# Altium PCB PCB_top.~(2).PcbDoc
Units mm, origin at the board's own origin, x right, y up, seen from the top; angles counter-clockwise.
Board outline 61.6 x 61.6 mm, 4 copper layers (TOP, 2, 3, BOTTOM), stack 1.719 mm thick; 9 components, 48 nets, 62 pads, 0 vias.
Unrouted connection lines stored in the file: 38.
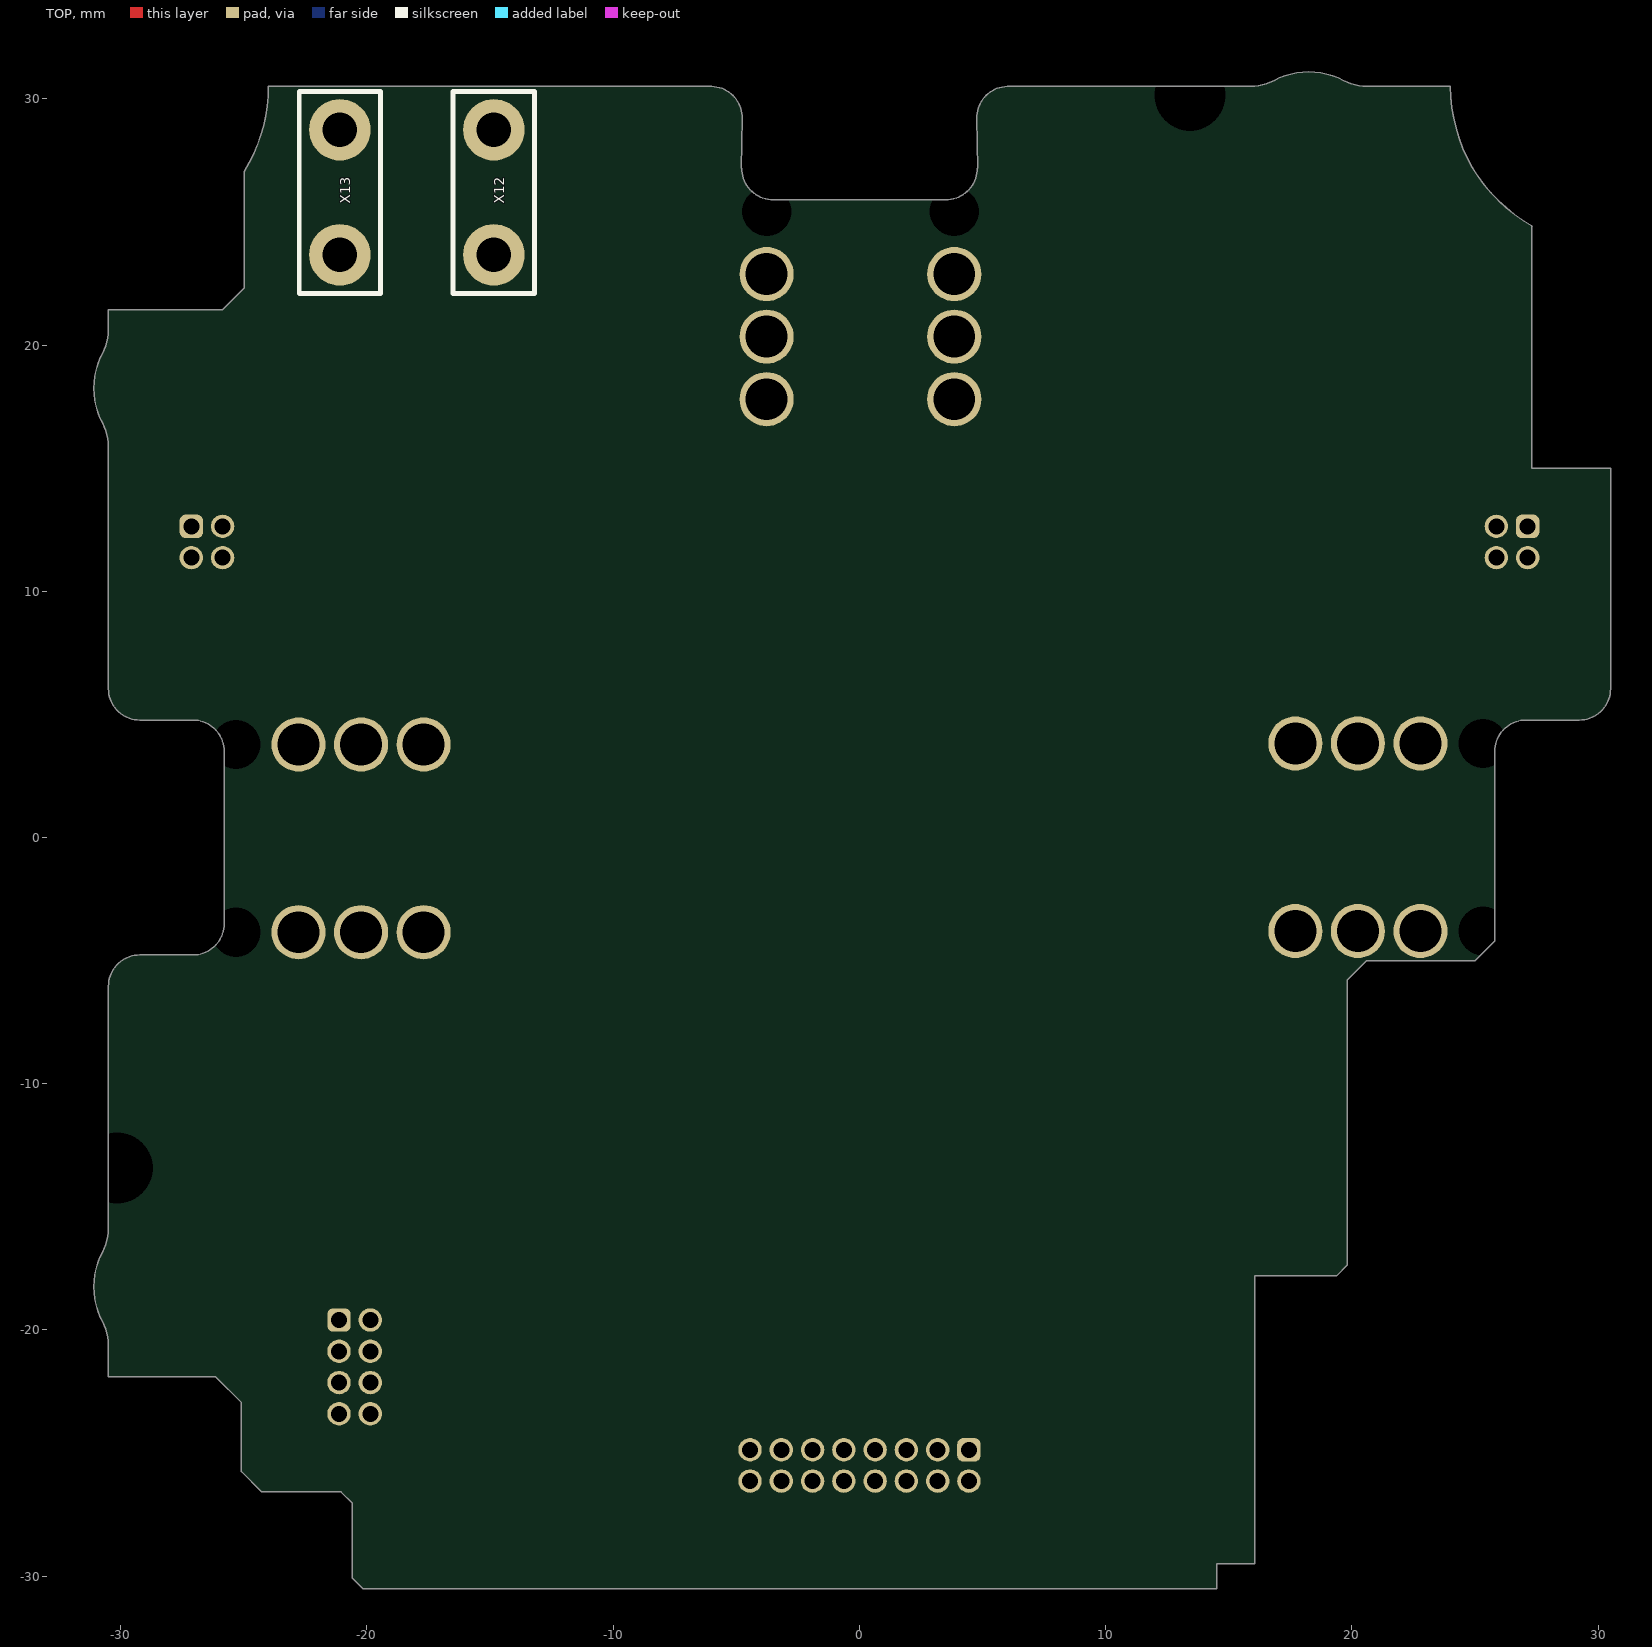
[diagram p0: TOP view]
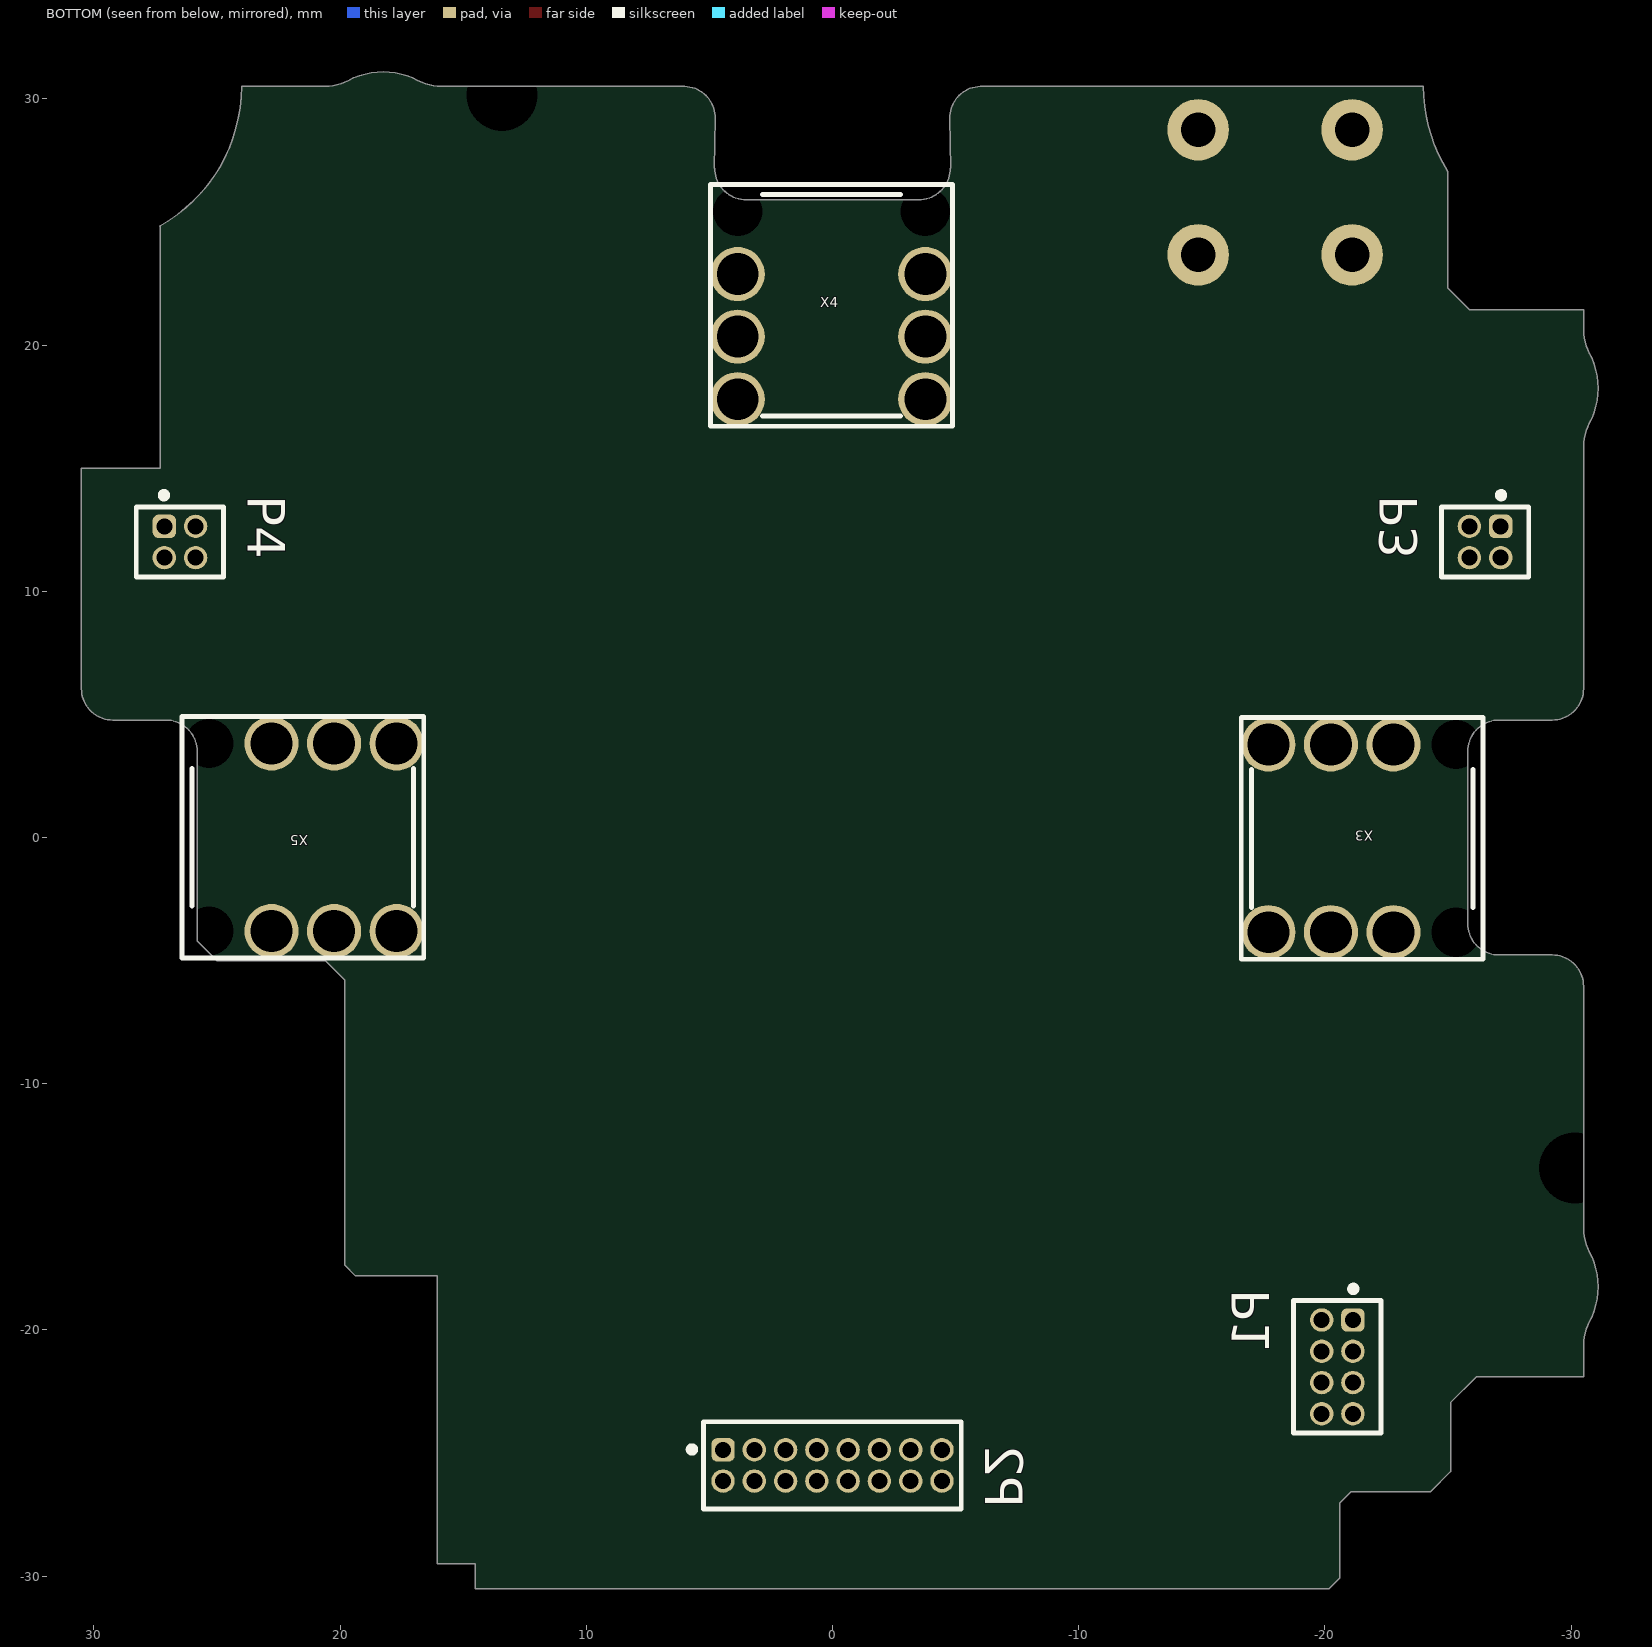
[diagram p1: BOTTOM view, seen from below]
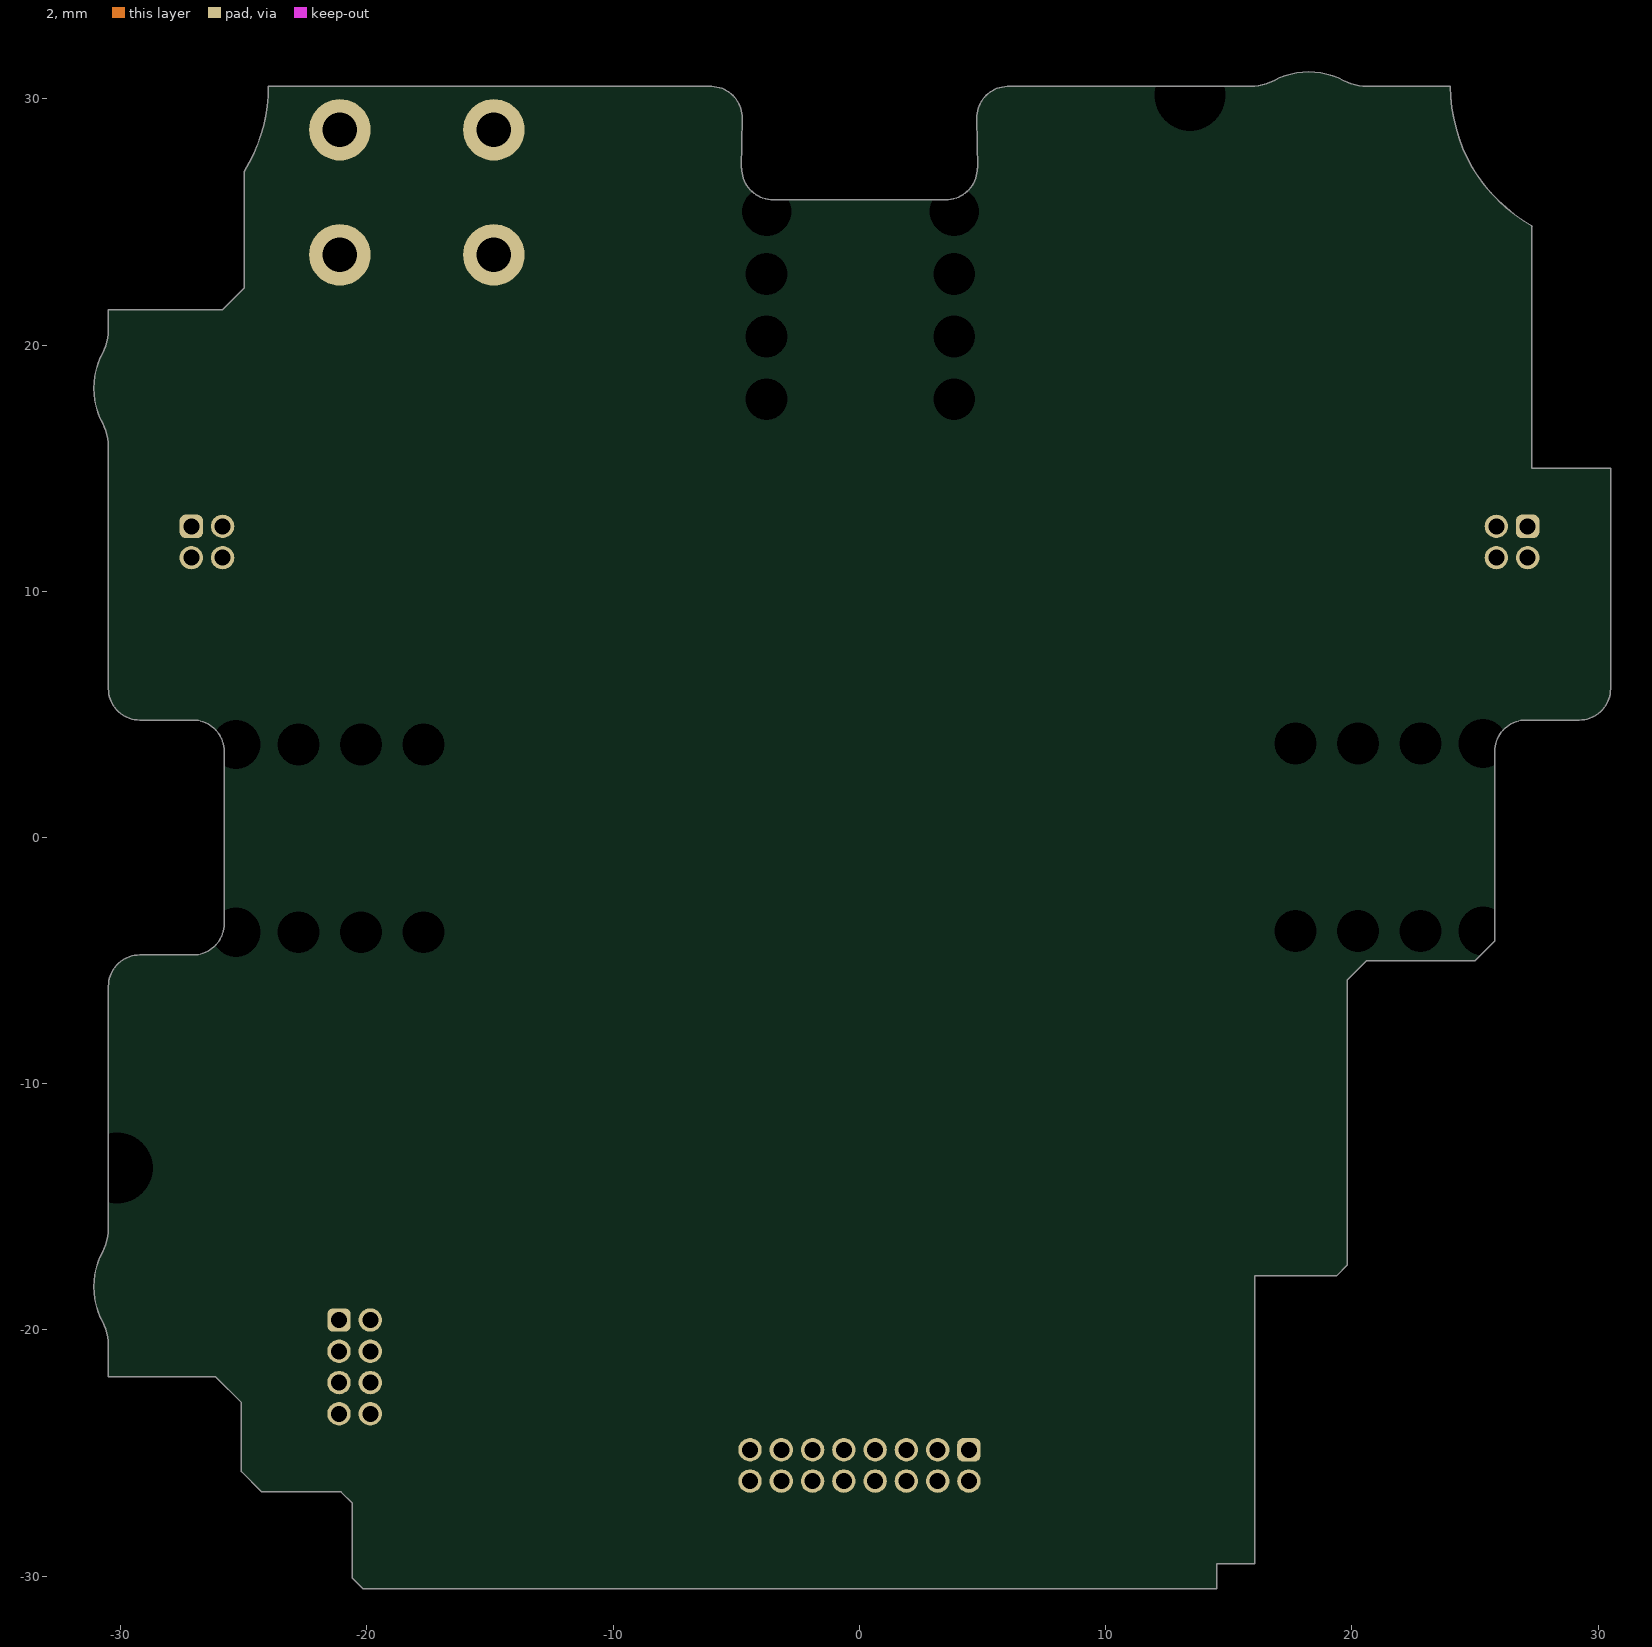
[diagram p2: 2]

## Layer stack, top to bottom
Top Solder: solder mask 0.01, Solder Resist, Dk 3.5
TOP: signal copper 0.07
Dielectric 1: prepreg 0.0711, PP-006, Dk 4.1
Dielectric 4: prepreg 0.2033, PP-006, Dk 4.1
2: signal copper 0.035
Dielectric 3: core 0.96, S1000-2, Dk 4.5
3: signal copper 0.035
Dielectric 2: prepreg 0.2033, PP-006, Dk 4.1
Dielectric 5: prepreg 0.0711, PP-006, Dk 4.1
BOTTOM: signal copper 0.07
Bottom Solder: solder mask 0.01, Solder Resist, Dk 3.5

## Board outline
-30.5,-20.612 ccw(c-32.5,-20.612) -30.738,-19.665 cw(c-28.095,-18.245) -30.738,-16.826 ccw(c-32.5,-15.879) -30.5,-15.879 -30.5,-6.04 cw(c-29.23,-6.04) -29.23,-4.77 -27.07,-4.77 ccw(c-27.07,-3.5) -25.8,-3.5 -25.8,3.5 ccw(c-27.07,3.5) -27.07,4.77 -29.23,4.77 cw(c-29.23,6.04) -30.5,6.04 -30.5,15.879 ccw(c-32.5,15.879) -30.738,16.826 cw(c-28.095,18.245) -30.738,19.665 ccw(c-32.5,20.612) -30.5,20.612 -30.5,21.442 -25.858,21.442 -24.988,22.312 -24.988,27.055 ccw(c-30.5,30.5) -24,30.5 -6,30.5 cw(c-6.034,29.233) -4.767,29.199 -4.799,27.185 -4.788,27.185 ccw(c-3.503,27.185) -3.503,25.9 3.503,25.9 ccw(c3.503,27.185) 4.788,27.185 4.799,27.185 4.767,29.199 cw(c6.034,29.233) 6,30.5 15.879,30.5 ccw(c15.879,32.5) 16.826,30.738 cw(c18.245,28.095) 19.665,30.738 ccw(c20.612,32.5) 20.612,30.5 24,30.5 ccw(c30.5,30.5) 27.318,24.832 27.3,24.842 27.3,15 30.5,15 30.5,6.04 cw(c29.23,6.04) 29.23,4.77 27.07,4.77 ccw(c27.07,3.5) 25.8,3.5 25.8,-4.205 25.005,-5 20.598,-5 19.8,-5.798 19.8,-17.373 19.368,-17.805 16.055,-17.805 16.055,-29.5 14.5,-29.5 14.5,-30.5 -20.175,-30.5 -20.6,-30.075 -20.6,-27.025 -21.05,-26.575 -24.275,-26.575 -25.1,-25.75 -25.1,-22.95 -26.15,-21.9 -30.5,-21.9

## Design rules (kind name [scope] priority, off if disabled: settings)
BoardOutlineClearance [All] p1: gap=0.5 ignorepadtopadclearanceinfootprint=FALSE
Clearance "Clearance TP Bottom" [InPadClass('Test pads') AND OnBottomLayer vs InPadClass('Test pads') AND OnBottomLayer] p1: gap=2.54 ignorepadtopadclearanceinfootprint=FALSE
Clearance "Clearance PE" [InNet('PE')] p2: gap=0.5 ignorepadtopadclearanceinfootprint=FALSE
Clearance "Clearance spacers" [InComponentClass('Spacer')] p3: gap=0.5 ignorepadtopadclearanceinfootprint=FALSE
Clearance "Clearance Polygon" [InPolygon vs InPolygon] p4: gap=0.5 ignorepadtopadclearanceinfootprint=FALSE
Clearance "Clearance All" [NOT InComponent('U1') AND NOT InPadClass('Exception pads')] p5: gap=0.2 ignorepadtopadclearanceinfootprint=FALSE
Clearance "Clearance Via" [IsVia vs IsPad And Not (InComponentClass('PowerComponents') Or InPadClass('Power pads'))] p6 off: gap=0.25 ignorepadtopadclearanceinfootprint=FALSE
ComponentClearance "ComponentClearance Wave Soldering" [InComponentClass('THT Components')] p1: gap=3 collisioncheckmode=3 verticalgap=2540 showdistances=TRUE
ComponentClearance "ComponentClearance Selective Soldering" [InComponentClass('Selective Soldering Component')] p2: gap=3 collisioncheckmode=3 verticalgap=2540 showdistances=TRUE
ComponentClearance [OnLayer('Top Layer') vs OnLayer('Top Layer')] p3: gap=0.203 collisioncheckmode=3 verticalgap=0.254 showdistances=FALSE
FabricationTestPointUsage TestPointUsage [InNetClass('All Nets')] p1 off: valid=0 allowmultiple=FALSE
FabricationTestpoint Testpoint [(InNetClass('All Nets')) And ((IsPad And (OnTopLayer Or OnBottomLayer)))] p1 off: side=2 testpointundercomponent=FALSE minsize=1 maxsize=2 preferedsize=1.2 minholesize=0 maxholesize=2 preferedholesize=1 testpointgrid=0.01 allowsidebottom=TRUE usegrid=TRUE gridtolerance=0
FanoutControl Fanout_BGA [IsBGA] p1: bgadir=Out bgaviamode=Centered fanoutstyle=Auto fanoutdirection=InThenOut viagrid=0.025 // Fanout_BGA (Default Rule)
FanoutControl Fanout_LCC [IsLCC] p2: bgadir=Out bgaviamode=Centered fanoutstyle=Auto fanoutdirection=InThenOut viagrid=0.025 // Fanout_LCC (Default Rule)
FanoutControl Fanout_SOIC [IsSOIC] p3: bgadir=Out bgaviamode=Centered fanoutstyle=Auto fanoutdirection=InThenOut viagrid=0.025 // Fanout_SOIC (Default Rule)
FanoutControl Fanout_Small [(CompPinCount < 5)] p4: bgadir=Out bgaviamode=Centered fanoutstyle=Auto fanoutdirection=InThenOut viagrid=0.025 // Fanout_Small (Default Rule)
FanoutControl Fanout_Default [All] p5: bgadir=Out bgaviamode=Centered fanoutstyle=Auto fanoutdirection=InThenOut viagrid=0.025 // Fanout_Default (Default Rule)
Height [All] p1: minheight=0 maxheight=40 prefheight=12.7
HoleSize [All] p1: absolutevalues=TRUE maxlimit=20 minlimit=0.15 maxpercent=80.000 minpercent=20.000
HoleToHoleClearance [All] p1: gap=0.15 allowstackedmicrovias=TRUE
MinimumAnnularRing [All] p1 off: minimumring=0.125
NetAntennae [All] p1 off: netantennaetolerance=0
PlaneClearance [All] p1: clearance=0.5
PlaneConnect [All] p1: planeconnectstyle=Direct reliefexpansion=0.508 reliefentries=4 reliefconductorwidth=0.254 reliefairgap=0.254
PolygonConnect "PolygonConnect Direct" [InPadClass('Direct pads')] p1: connectstyle=Direct reliefconductorwidth=0.254 reliefentries=4 polygonreliefangle="90 Angle" airgapwidth=0.254
PolygonConnect "PolygonConnect TestPads" [InPadClass('Test pads')] p2: connectstyle=Direct reliefconductorwidth=0.254 reliefentries=4 polygonreliefangle="90 Angle" airgapwidth=0.254
PolygonConnect PolygonConnect-PowerPads [InPadClass('Power pads')] p3: connectstyle=Relief reliefconductorwidth=1 reliefentries=4 polygonreliefangle="90 Angle" airgapwidth=0.2
PolygonConnect "PolygonConnect Via" [IsVia] p4: connectstyle=Direct reliefconductorwidth=0.254 reliefentries=4 polygonreliefangle="90 Angle" airgapwidth=0.254
PolygonConnect "PolygonConnect All" [All] p5: connectstyle=Relief reliefconductorwidth=0.3 reliefentries=4 polygonreliefangle="90 Angle" airgapwidth=0.25
RoutingCorners [All] p1: cornerstyle=45-Degree minsetback=2 maxsetback=2
RoutingVias [All] p1: holewidth=0.2 width=0.5 viastyle="Through Hole" minholewidth=0.2 minwidth=0.5 maxholewidth=1 maxwidth=2 useviatemplates=TRUE viatemplateguid#1={C91082AD-6814-4CF8-9952-BA175974D977} viatemplateguid#2={F9BC3B68-C7FA-485B-9147-DE2A793F0151} viatemplatename#1=v05h02 viatemplatename#2=v06h03
SilkToSolderMaskClearance SilkscreenOverComponentPads [IsPad] p1: minsilkscreentomaskgap=0.254 clearancetoexposedcopper=TRUE
SolderMaskExpansion [All] p1: expansion=0.1 istentingtop=FALSE
SupplyNets "Schematic Supply Nets" [InNet('24V/12V')] p1: voltage=0.000
SupplyNets "Schematic Supply Nets_2" [InNet('24V')] p2: voltage=0.000
SupplyNets "Schematic Supply Nets_3" [InNet('GND')] p3: voltage=0.000
SupplyNets "Schematic Supply Nets_1" [InNet('DC_LINK')] p4: voltage=0.000
SupplyNets "Schematic Supply Nets_9" [InNet('5V')] p5: voltage=0.000
Width [All] p1: maxlimit=10 minlimit=0.1 preferedwidth=0.25
14 further rules are at their usual default settings.

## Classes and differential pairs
pad class "Direct pads": X3-1 X4-1 X5-1
component class Power_Mosfet: X3 X4 X5
pad class "Power pads": X13-1
component class Main: P1 P2 P3 P4 X12 X13

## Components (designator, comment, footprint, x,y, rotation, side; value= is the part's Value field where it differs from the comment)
P1 "62200821121" 62200821121 -20.5,-21.5 r270 bottom locked
P2 "62201621121" 62201621121 0,-25.5 r180 bottom locked
P3 "62200421121" 62200421121#1 -26.5,12 r270 bottom
P4 "62200421121" 62200421121#2 26.5,12 r270 bottom locked
X3 "K_WURTH_7461063" FPR_K_1P_WURTH -21.51,-0.035 r270 bottom locked
X4 "K_WURTH_7461063" FPR_K_1P_WURTH 0.04,21.61 r180 bottom locked
X5 "K_WURTH_7461063" FPR_K_1P_WURTH 21.51,0.01 r90 bottom locked
X12 "C_TE_FASTON_6.3_P5.08" FPR_TAB_6.3_P5.08_Pokončni -14.85,26.2 r90 top locked
X13 "C_TE_FASTON_6.3_P5.08" FPR_TAB_6.3_P5.08_Pokončni -21.1,26.2 r90 top locked

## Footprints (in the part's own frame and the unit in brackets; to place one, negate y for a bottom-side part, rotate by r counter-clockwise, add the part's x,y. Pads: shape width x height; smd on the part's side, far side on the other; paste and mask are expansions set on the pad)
62200421121#1 [mm]
  rrect50% 0.95x0.95 hole 0.65: 1(-0.635,0.635)
  round 0.95 hole 0.65: 2(-0.635,-0.635) 3(0.635,0.635) 4(0.635,-0.635)
  silkscreen extent -2.02,-1.78 1.42,1.78, body extent -1.27,-1.7 1.27,1.7, height 5.33
62200421121#2 [mm]
  rrect50% 0.95x0.95 hole 0.65: 1(-0.635,-0.635)
  round 0.95 hole 0.65: 2(-0.635,0.635) 3(0.635,-0.635) 4(0.635,0.635)
  silkscreen extent -2.02,-1.78 1.42,1.78, body extent -1.27,-1.7 1.27,1.7, height 5.33
62200821121 [mm]
  rrect50% 0.95x0.95 hole 0.65: 1(-1.905,0.635)
  round 0.95 hole 0.65: 2(-1.905,-0.635) 3(-0.635,0.635) 4(-0.635,-0.635) 5(0.635,0.635) 6(0.635,-0.635) 7(1.905,0.635) 8(1.905,-0.635)
  silkscreen extent -3.29,-1.78 2.69,1.78, body extent -2.54,-1.7 2.54,1.7, height 5.33
62201621121 [mm]
  rrect50% 0.95x0.95 hole 0.65: 1(-4.445,0.635)
  round 0.95 hole 0.65: 2(-4.445,-0.635) 3(-3.175,0.635) 4(-3.175,-0.635) 5(-1.905,0.635) 6(-1.905,-0.635) 7(-0.635,0.635) 8(-0.635,-0.635) 9(0.635,0.635) 10(0.635,-0.635) 11(1.905,0.635) 12(1.905,-0.635) 13(3.175,0.635) 14(3.175,-0.635) 15(4.445,0.635) 16(4.445,-0.635)
  silkscreen extent -5.83,-1.78 5.23,1.78, body extent -5.08,-1.7 5.08,1.7, height 5.33
FPR_K_1P_WURTH [mm]
  round 2.2 / inner round 0 / far side round 2.2 hole 1.7: 1(-3.81,-1.27) 1(-3.81,-3.81) 1(-3.81,1.27) 1(3.81,-3.81) 1(3.81,-1.27) 1(3.81,1.27)
  round 0 hole 2 unplated: 1(-3.81,3.81) 1(3.81,3.81)
  silkscreen extent -4.91,-4.91 4.91,4.91, body extent -4.5,-4.5 4.5,4.5, height 14
FPR_TAB_6.3_P5.08_Pokončni [mm]
  round 2.5 hole 1.4: 1(-2.54,0) 1(2.54,0)
  silkscreen extent -4.1,-1.65 4.1,1.65, body extent -3.96,-1.54 3.96,1.54, height 10.21

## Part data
P1: library part CMP-1502-00947-4, "THT Vertical Pin Header WR-PHD, Pitch 1.27 mm, Dual Row, 8 pins", Color=Black, Contact Resistance=20mΩ, Current Rating=1A
P2: library part CMP-1502-00950-4, "THT Vertical Pin Header WR-PHD, Pitch 1.27 mm, Dual Row, 16 pins", Color=Black, Contact Resistance=20mΩ, Current Rating=1A
P3 P4: library part CMP-1502-00946-4, "THT Vertical Pin Header WR-PHD, Pitch 1.27 mm, Dual Row, 4 pins", Color=Black, Contact Resistance=20mΩ, Current Rating=1A
X3 X4 X5: library part K_WURTH_7461063-4, "Connector POWER Wurth 7461063", Current=160, Manufacturer="WURTH ELEKTRONIK", Manufacturer code=7461063, TemperatureGrade=-40...150, Voltage=300
X12 X13: library part C_TE_FASTON_6.3_P5.08-4, "FASTON 6.3 P5.08 Pokončni", Current=-, Manufacturer="TE CONNECTIVITY", Manufacturer code=1217136-1, TemperatureGrade="-30...110 °C", Voltage=/

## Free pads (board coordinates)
  round 0 hole 2.9 unplated paste-2539.97 mask+0.1: 107(-30.146,-13.422) 991(13.422,30.147)

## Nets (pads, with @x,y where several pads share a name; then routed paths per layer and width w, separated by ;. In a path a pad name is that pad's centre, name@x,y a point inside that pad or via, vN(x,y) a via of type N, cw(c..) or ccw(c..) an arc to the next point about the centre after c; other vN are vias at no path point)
5V: P1.7
24V/12V: P1.1 P1.2
DC_LINK: P3.2 P3.4 P4.2 P4.4
GATE_UH: 
GATE_UL: 
GATE_VH: 
GATE_VL: 
GATE_WH: 
GATE_WL: 
GND: P1.3 P1.5 P1.6 P2.3 P2.6 P2.10 P2.13 P2.14 P3.3 P4.1 P4.3 X13.1
I_D_SPI_MISO: P2.16
NetC7_1: 
NetC8_1: 
NetC9_1: 
NetC10_1: 
NetC10_2: 
NetC11_1: 
NetC11_2: 
NetC13_2: 
NetC14_1: 
NetC14_2: 
NetIC3_36: 
NetIC3_45: 
NetIC3_46: 
O_D_EN_GATE: P2.2
O_D_PWM_UH: P2.1
O_D_PWM_UL: P2.5
O_D_PWM_VH: P2.7
O_D_PWM_VL: P2.9
O_D_PWM_WH: P2.11
O_D_PWM_WL: P2.15
O_D_SPI_CLK: P2.8
O_D_SPI_CS: P2.4
O_D_SPI_MOSI: P2.12
Ohisje: P3.1
SH_U: X3.1
SH_V: X4.1
SH_W: X5.1
SL_U: 
SL_V: 
SL_W: 
SN_U: 
SN_V: 
SO_U: P1.4
SO_V: P1.8
SP_U: 
SP_V: 
V_BAT_PLUS: X12.1

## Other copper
2:
  pour cut-out: -4.9,26.2 -4.9,16.622 5.1,16.622 5.1,26.2

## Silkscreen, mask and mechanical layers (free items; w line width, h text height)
Mechanical 3:
  lines w0.2: -4.799,27.185 -4.767,29.199 ccw(c-6.034,29.233) -6,30.5 -24,30.5 cw(c-30.5,30.5) -24.988,27.055 -24.988,22.312 -25.858,21.442 -30.5,21.442 -30.5,20.612 cw(c-32.5,20.612) -30.738,19.665 ccw(c-28.095,18.245) -30.738,16.826 cw(c-32.5,15.879) -30.5,15.879 -30.5,7.5 -30.5,6.04 ccw(c-29.23,6.04) -29.23,4.77 -27.07,4.77 cw(c-27.07,3.5) -25.8,3.5 -25.8,-3.5 cw(c-27.07,-3.5) -27.07,-4.77 -29.23,-4.77 ccw(c-29.23,-6.04) -30.5,-6.04 -30.5,-7.5 -30.5,-15.879 cw(c-32.5,-15.879) -30.738,-16.826 ccw(c-28.095,-18.245) -30.738,-19.665 cw(c-32.5,-20.612) -30.5,-20.612 -30.5,-21.9 -26.15,-21.9 -25.1,-22.95 -25.1,-25.75 -24.275,-26.575 -21.05,-26.575 -20.6,-27.025 -20.6,-30.075 -20.175,-30.5 -15.879,-30.5 14.5,-30.5 14.5,-29.5 16.055,-29.5 16.055,-17.805 19.368,-17.805 19.8,-17.373 19.8,-5.798 20.598,-5 25.005,-5 25.8,-4.205 25.8,3.5 cw(c27.07,3.5) 27.07,4.77 29.23,4.77 ccw(c29.23,6.04) 30.5,6.04 30.5,7.5 30.5,15 27.3,15 27.3,24.842 ; -4.788,27.185 ccw(c-3.503,27.185) -3.503,25.9 ; -3.5,25.9 0,25.9 3.5,25.9 ; 3.503,25.9 ccw(c3.503,27.185) 4.788,27.185 ; 4.799,27.185 4.767,29.199 cw(c6.034,29.233) 6,30.5 ; 6.1,30.5 15.879,30.5 ccw(c15.879,32.5) 16.826,30.738 cw(c18.245,28.095) 19.665,30.738 ccw(c20.612,32.5) 20.612,30.5 24,30.5 ccw(c30.5,30.5) 27.318,24.832
Mechanical 4:
  circle w0.254: c0,0 r26.5
  circle w0.1: c0,0 r33.5
Mechanical 7:
  circle w0.1: c-27,-21.5 r4.3
  circle w0.1: c-27,-19.5 r4.3
  circle w0.1: c17.5,-27.5 r3.75
  circle w0.1: c17.5,-22.5 r3.75
  circle w0.1: c0.5,-27.5 r3.75
  circle w0.1: c2.5,-27.5 r3.75
  circle w0.1: c4.5,-27.5 r3.75
  circle w0.1: c-12.42,-26 r4.3
  circle w0.1: c-8.46,-26 r4.3
  circle w0.1: c-4.5,-26 r4.3
Overlay print TOP:
  text "V" at -5.296,14.224 h2
  text "U" at -19.221,5.174 h2
  text "W" at 18.898,-6.825 h2
Mechanical 28:
  circle w0.254: c-17.7,-3.845 r0.835
  circle w0.254: c-20.24,-3.845 r0.835
  circle w0.254: c-22.78,-3.845 r0.835
  circle w0.254: c-17.7,3.775 r0.835
  circle w0.254: c-20.24,3.775 r0.835
  circle w0.254: c-22.78,3.775 r0.835
  circle w0.254: c-3.77,17.8 r0.835
  circle w0.254: c-3.77,20.34 r0.835
  circle w0.254: c-3.77,22.88 r0.835
  circle w0.254: c3.85,17.8 r0.835
  circle w0.254: c3.85,20.34 r0.835
  circle w0.254: c3.85,22.88 r0.835
  circle w0.254: c22.78,-3.8 r0.835
  circle w0.254: c20.24,-3.8 r0.835
  circle w0.254: c17.7,-3.8 r0.835
  circle w0.254: c22.78,3.82 r0.835
  circle w0.254: c20.24,3.82 r0.835
  circle w0.254: c17.7,3.82 r0.835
